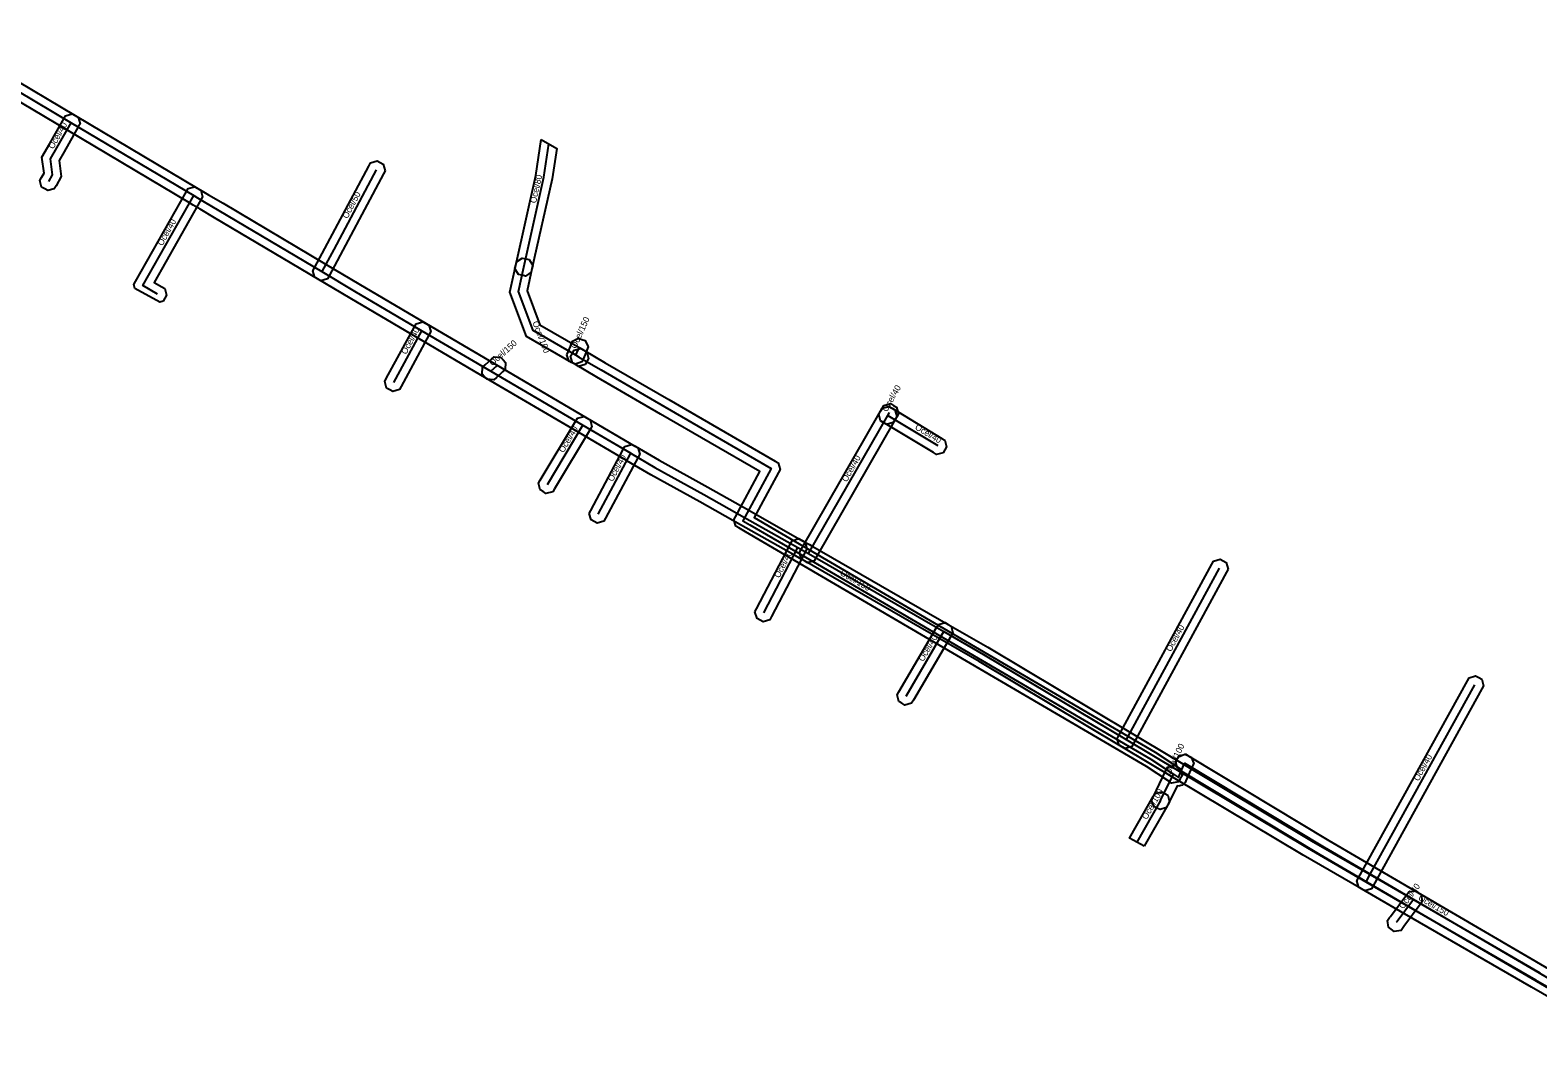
# Model space of a CAD drawing. Extents: x -749340 to -748632, y -965391 to -964902.
# Drawn here: x -749163.1 to -748982.7, y -965119.7 to -964997.5 of the extents above; entities that cross this region are included whole.
import ezdxf

# ---------------------------------------------------------------- set-up
doc = ezdxf.new("R2010")
doc.units = 0
for name, color, linetype in [('1', 7, 'Continuous'), ('18', 7, 'Continuous'), ('20', 7, 'Continuous'), ('28', 7, 'Continuous'), ('30', 7, 'Continuous')]:
    doc.layers.add(name, color=color, linetype=linetype)

msp = doc.modelspace()

# ---------------------------------------------------------------- linework, layer by layer
at = {"layer": '1'}
for points in [[(-749174.95, -964997.45), (-749157.74, -965007.68), (-749143.06, -965016.4), (-749142.6, -965016.68), (-749141.79, -965017.15), (-749140.06, -965018.18), (-749127.73, -965025.51), (-749123.82, -965027.83), (-749115.76, -965032.57), (-749107.52, -965037.41), (-749096.48, -965043.89), (-749090.78, -965047.24), (-749090.73, -965047.26), (-749087.87, -965048.94), (-749082.03, -965052.15), (-749077.15, -965054.91), (-749070.78, -965058.52), (-749069.88, -965059.03), (-749069.5, -965059.24), (-749053.3, -965068.57), (-749048.55, -965071.3), (-749031.48, -965081.51), (-749009.8, -965094.47), (-749002.81, -965098.51), (-748997.7, -965101.46), (-748982.49, -965110.26)], [(-748970.03, -965119.74), (-748983.49, -965111.99), (-748998.7, -965103.2), (-749003.81, -965100.24), (-749010.81, -965096.2), (-749032.5, -965083.23), (-749049.56, -965073.03), (-749054.3, -965070.3), (-749070.49, -965060.98), (-749070.87, -965060.76), (-749071.76, -965060.26), (-749078.14, -965056.65), (-749083, -965053.9), (-749088.86, -965050.68), (-749091.73, -965048.99), (-749091.77, -965048.97), (-749097.5, -965045.61), (-749108.53, -965039.13), (-749116.77, -965034.29), (-749124.83, -965029.55), (-749128.75, -965027.22), (-749141.08, -965019.9), (-749142.81, -965018.87), (-749143.62, -965018.4), (-749144.08, -965018.12), (-749158.76, -965009.4), (-749175.98, -964999.17)]]:
    msp.add_lwpolyline(points, dxfattribs=at)
for points in [[(-749161.99, -965015.45), (-749161.78, -965015.09), (-749161.48, -965014.56), (-749161.73, -965012.67), (-749160.8, -965011.03), (-749159.12, -965008.05), (-749158.91, -965007.69), (-749158.11, -965007.47), (-749157.76, -965007.67), (-749157.39, -965007.88), (-749157.17, -965008.67), (-749157.38, -965009.03), (-749159.06, -965012.02), (-749159.66, -965013.07), (-749159.41, -965014.96), (-749160.04, -965016.07), (-749160.25, -965016.43), (-749161.04, -965016.65), (-749161.4, -965016.45), (-749161.77, -965016.24)], [(-749102, -965010.55), (-749100.13, -965011.62), (-749100.67, -965015.23), (-749103.09, -965026.03), (-749103.18, -965026.43), (-749103.88, -965026.88), (-749104.28, -965026.79), (-749104.69, -965026.7), (-749105.13, -965025.99), (-749105.04, -965025.59), (-749102.64, -965014.87)], [(-749120.65, -965014.3), (-749120.84, -965014.66), (-749127.36, -965026.84), (-749127.56, -965027.2), (-749128.35, -965027.44), (-749128.71, -965027.25), (-749129.08, -965027.05), (-749129.32, -965026.26), (-749129.12, -965025.89), (-749122.6, -965013.72), (-749122.41, -965013.35), (-749121.62, -965013.11), (-749121.25, -965013.31), (-749120.89, -965013.51)], [(-749147.23, -965029.89), (-749147.64, -965030.01), (-749150.61, -965028.36), (-749150.74, -965027.9), (-749150.54, -965027.54), (-749144.44, -965016.77), (-749144.24, -965016.41), (-749143.44, -965016.19), (-749143.08, -965016.39), (-749142.72, -965016.59), (-749142.5, -965017.39), (-749142.7, -965017.75), (-749148.3, -965027.66), (-749147.4, -965028.17), (-749147.04, -965028.37), (-749146.82, -965029.17), (-749147.02, -965029.53)], [(-749097.54, -965037.7), (-749097.9, -965037.49), (-749098.35, -965037.23), (-749103.76, -965034.11), (-749105.76, -965028.82), (-749105.04, -965025.59), (-749104.95, -965025.19), (-749104.25, -965024.74), (-749103.84, -965024.83), (-749103.44, -965024.92), (-749103, -965025.62), (-749103.09, -965026.03), (-749103.68, -965028.67), (-749102.14, -965032.73), (-749097.35, -965035.49), (-749096.9, -965035.76), (-749096.54, -965035.96), (-749096.32, -965036.76), (-749096.53, -965037.12), (-749096.74, -965037.48)], [(-749120.71, -965039.52), (-749120.52, -965039.16), (-749117.14, -965032.95), (-749116.95, -965032.59), (-749116.15, -965032.35), (-749115.79, -965032.55), (-749115.42, -965032.75), (-749115.19, -965033.54), (-749115.39, -965033.9), (-749118.76, -965040.11), (-749118.96, -965040.48), (-749119.75, -965040.71), (-749120.11, -965040.52), (-749120.48, -965040.32)], [(-749098.93, -965036.33), (-749098.76, -965035.95), (-749098.48, -965035.33), (-749098.39, -965035.08), (-749098.25, -965034.69), (-749097.51, -965034.33), (-749097.12, -965034.47), (-749096.72, -965034.61), (-749096.37, -965035.35), (-749096.51, -965035.74), (-749096.63, -965036.08), (-749096.94, -965036.77), (-749097.11, -965037.15), (-749097.89, -965037.44), (-749098.26, -965037.27), (-749098.64, -965037.1)], [(-749073.6, -965050.38), (-749076.51, -965055.79), (-749028.51, -965083.88), (-749025.79, -965085.67), (-749025.45, -965085.89), (-749025.28, -965086.71), (-749025.51, -965087.05), (-749025.74, -965087.4), (-749026.55, -965087.56), (-749026.89, -965087.34), (-749029.56, -965085.58), (-749077.53, -965057.51), (-749078.35, -965057.03), (-749078.7, -965056.83), (-749078.92, -965056.05), (-749078.73, -965055.7), (-749075.82, -965050.28), (-749087.71, -965043.4), (-749095.32, -965038.99), (-749097.9, -965037.49), (-749098.26, -965037.28), (-749098.47, -965036.48), (-749098.26, -965036.12), (-749098.05, -965035.76), (-749097.25, -965035.55), (-749096.9, -965035.76), (-749094.32, -965037.26), (-749086.71, -965041.67), (-749073.98, -965049.04), (-749073.63, -965049.24), (-749073.41, -965050.02)], [(-749109, -965037.8), (-749108.69, -965037.52), (-749107.94, -965036.85), (-749107.63, -965036.57), (-749106.81, -965036.62), (-749106.53, -965036.93), (-749106.25, -965037.23), (-749106.3, -965038.06), (-749106.6, -965038.34), (-749107.35, -965039.01), (-749107.66, -965039.29), (-749108.49, -965039.24), (-749108.77, -965038.94), (-749109.04, -965038.63)], [(-749071.07, -965059.97), (-749070.86, -965059.61), (-749061.38, -965043.07), (-749061.18, -965042.71), (-749060.38, -965042.49), (-749060.02, -965042.7), (-749059.66, -965042.91), (-749059.44, -965043.71), (-749059.65, -965044.07), (-749069.13, -965060.61), (-749069.33, -965060.97), (-749070.13, -965061.19), (-749070.49, -965060.98), (-749070.85, -965060.77)], [(-749061.59, -965043.43), (-749061.38, -965043.07), (-749061.18, -965042.72), (-749060.97, -965042.36), (-749060.17, -965042.15), (-749059.82, -965042.36), (-749059.46, -965042.57), (-749059.24, -965043.36), (-749059.45, -965043.72), (-749059.65, -965044.07), (-749059.86, -965044.43), (-749060.66, -965044.64), (-749061.02, -965044.44), (-749061.38, -965044.23)], [(-749060.35, -965042.5), (-749060, -965042.71), (-749054.03, -965046.31), (-749053.67, -965046.52), (-749053.47, -965047.33), (-749053.69, -965047.68), (-749053.9, -965048.04), (-749054.7, -965048.24), (-749055.06, -965048.02), (-749061.03, -965044.43), (-749061.39, -965044.21), (-749061.59, -965043.41), (-749061.37, -965043.05), (-749061.16, -965042.7)], [(-749102.33, -965051.66), (-749102.11, -965051.31), (-749097.85, -965044.23), (-749097.63, -965043.88), (-749096.83, -965043.68), (-749096.47, -965043.89), (-749096.12, -965044.1), (-749095.92, -965044.91), (-749096.13, -965045.26), (-749100.4, -965052.34), (-749100.61, -965052.7), (-749101.42, -965052.9), (-749101.77, -965052.68), (-749102.12, -965052.47)], [(-749096.25, -965055.29), (-749096.06, -965054.93), (-749092.16, -965047.63), (-749091.96, -965047.27), (-749091.17, -965047.03), (-749090.8, -965047.22), (-749090.44, -965047.42), (-749090.2, -965048.21), (-749090.39, -965048.58), (-749094.29, -965055.87), (-749094.49, -965056.23), (-749095.28, -965056.47), (-749095.65, -965056.28), (-749096.01, -965056.08)], [(-749076.41, -965067.09), (-749076.22, -965066.73), (-749072.16, -965058.93), (-749071.96, -965058.56), (-749071.17, -965058.31), (-749070.81, -965058.5), (-749070.44, -965058.69), (-749070.19, -965059.48), (-749070.38, -965059.85), (-749074.44, -965067.65), (-749074.63, -965068.02), (-749075.42, -965068.27), (-749075.79, -965068.08), (-749076.16, -965067.88)], [(-749019.78, -965061.97), (-749019.97, -965062.33), (-749031.11, -965082.85), (-749031.31, -965083.21), (-749032.1, -965083.45), (-749032.47, -965083.25), (-749032.83, -965083.05), (-749033.07, -965082.26), (-749032.87, -965081.89), (-749021.73, -965061.38), (-749021.54, -965061.02), (-749020.74, -965060.78), (-749020.38, -965060.98), (-749020.01, -965061.18)], [(-749059.39, -965077.01), (-749059.18, -965076.65), (-749054.67, -965068.93), (-749054.46, -965068.57), (-749053.66, -965068.36), (-749053.3, -965068.57), (-749052.94, -965068.78), (-749052.73, -965069.58), (-749052.94, -965069.94), (-749057.45, -965077.66), (-749057.66, -965078.02), (-749058.46, -965078.23), (-749058.82, -965078.02), (-749059.18, -965077.81)], [(-748989.21, -965075.94), (-748989.41, -965076.3), (-749002.44, -965099.86), (-749002.64, -965100.22), (-749003.43, -965100.45), (-749003.8, -965100.25), (-749004.16, -965100.05), (-749004.39, -965099.25), (-749004.19, -965098.89), (-748991.16, -965075.34), (-748990.96, -965074.97), (-748990.17, -965074.74), (-748989.8, -965074.95), (-748989.44, -965075.15)], [(-749025.68, -965087.92), (-749025.9, -965087.89), (-749026.97, -965090.1), (-749027.15, -965090.48), (-749027.93, -965090.75), (-749028.3, -965090.57), (-749028.68, -965090.39), (-749028.95, -965089.61), (-749028.77, -965089.24), (-749027.24, -965086.07), (-749027.05, -965085.66), (-749026.61, -965085.54), (-749026.18, -965085.42), (-749025.91, -965084.79), (-749025.74, -965084.41), (-749024.96, -965084.11), (-749024.59, -965084.28), (-749024.21, -965084.45), (-749023.91, -965085.22), (-749024.08, -965085.6), (-749024.83, -965087.3), (-749024.92, -965087.51), (-749025.25, -965087.8), (-749025.46, -965087.86)], [(-748969.52, -965119.09), (-748969.88, -965118.88), (-748998.11, -965102.38), (-749008.77, -965096.15), (-749025.51, -965086.05), (-749025.86, -965085.84), (-749026.06, -965085.03), (-749025.85, -965084.68), (-749025.63, -965084.32), (-749024.83, -965084.12), (-749024.47, -965084.34), (-749007.75, -965094.43), (-748997.1, -965100.66), (-748968.87, -965117.16), (-748968.51, -965117.37), (-748968.3, -965118.17), (-748968.51, -965118.53), (-748968.72, -965118.88)], [(-749029.85, -965095.12), (-749031.6, -965094.15), (-749028.74, -965089.17), (-749028.53, -965088.81), (-749027.73, -965088.6), (-749027.37, -965088.8), (-749027.01, -965089.01), (-749026.8, -965089.81), (-749027, -965090.17)], [(-748996.56, -965101.78), (-748996.81, -965102.12), (-748998.76, -965104.74), (-748998.86, -965104.87), (-748999.1, -965105.2), (-748999.92, -965105.32), (-749000.26, -965105.07), (-749000.59, -965104.83), (-749000.71, -965104.01), (-749000.46, -965103.67), (-749000.36, -965103.54), (-748998.41, -965100.92), (-748998.16, -965100.59), (-748997.34, -965100.47), (-748997.01, -965100.72), (-748996.68, -965100.96)]]:
    msp.add_lwpolyline(points, close=True, dxfattribs=at)
at = {"layer": '18'}
for points in [[(-749175.47, -964998.31), (-749158.25, -965008.54), (-749143.57, -965017.26), (-749143.11, -965017.54), (-749142.3, -965018.01), (-749140.57, -965019.04), (-749128.24, -965026.36), (-749124.33, -965028.69), (-749116.26, -965033.43), (-749108.02, -965038.27), (-749096.99, -965044.75), (-749091.28, -965048.1), (-749091.23, -965048.13), (-749088.37, -965049.81), (-749082.51, -965053.02), (-749077.65, -965055.78), (-749071.27, -965059.39), (-749070.37, -965059.9), (-749070, -965060.11), (-749053.8, -965069.43), (-749049.06, -965072.17), (-749031.99, -965082.37), (-749010.3, -965095.33), (-749003.31, -965099.38), (-748998.2, -965102.33), (-748982.99, -965111.13), (-748969.53, -965118.87)], [(-749160.91, -965015.58), (-749160.45, -965014.76), (-749160.7, -965012.87), (-749159.93, -965011.52), (-749158.25, -965008.54)], [(-749121.72, -965014.19), (-749126.81, -965023.69), (-749128.24, -965026.36)], [(-749147.89, -965029.04), (-749149.67, -965028.03), (-749143.57, -965017.26)], [(-749119.64, -965039.64), (-749116.26, -965033.43)], [(-749108.02, -965038.27), (-749107.27, -965037.59)], [(-749070, -965060.11), (-749060.52, -965043.57)], [(-749060.52, -965043.57), (-749060.32, -965043.22)], [(-749060.52, -965043.57), (-749054.54, -965047.17)], [(-749101.25, -965051.83), (-749096.99, -965044.75)], [(-749095.18, -965055.4), (-749091.28, -965048.1)], [(-749075.33, -965067.19), (-749071.27, -965059.39)], [(-749020.85, -965061.86), (-749031.99, -965082.37)], [(-749058.32, -965077.15), (-749054.16, -965070.04), (-749053.8, -965069.43)], [(-748990.29, -965075.82), (-749002.82, -965098.49), (-749003.31, -965099.38)]]:
    msp.add_lwpolyline(points, dxfattribs=at)
at = {"layer": '28'}
for points in [[(-749104.06, -965025.81), (-749101.66, -965015.05), (-749101.07, -965011.08)], [(-749097.4, -965036.62), (-749097.85, -965036.36), (-749102.95, -965033.42), (-749104.72, -965028.75), (-749104.06, -965025.81)], [(-749097.85, -965036.36), (-749097.56, -965035.71), (-749097.45, -965035.41)], [(-749097.4, -965036.62), (-749094.82, -965038.12), (-749087.21, -965042.54), (-749074.48, -965049.9), (-749077.85, -965056.17), (-749077.03, -965056.65), (-749071.53, -965059.87), (-749029.03, -965084.72), (-749026.34, -965086.5)], [(-749027.87, -965089.67), (-749026.34, -965086.5), (-749025.74, -965086.9), (-749024.99, -965085.2)], [(-748969.37, -965118.02), (-748997.61, -965101.52), (-749008.26, -965095.29), (-749024.99, -965085.2)], [(-749027.87, -965089.67), (-749030.72, -965094.63)], [(-748997.61, -965101.52), (-748999.56, -965104.14), (-748999.66, -965104.27)]]:
    msp.add_lwpolyline(points, dxfattribs=at)

# ---------------------------------------------------------------- texts
at = {"layer": '20'}
for s, rotation, p in [('Ocel/40', 60.4569, (-749160.37, -965011.75)), ('Ocel/50', 61.8315, (-749125.18, -965020.08)), ('Ocel/40', 60.4945, (-749147.32, -965023.33)), ('Ocel/40', 61.4873, (-749118.15, -965036.33)), ('Ocel/150', 41.9027, (-749107.81, -965037.7)), ('Ocel/40', 59.9706, (-749060.62, -965043.2)), ('Ocel/40', 58.934, (-749099.32, -965048.09)), ('Ocel/40', 328.946, (-749057.33, -965045.17)), ('Ocel/40', 61.8644, (-749093.43, -965051.55)), ('Ocel/40', 60.185, (-749065.43, -965051.6)), ('Ocel/40', 62.4967, (-749073.5, -965063.09)), ('Ocel/40', 61.5057, (-749026.62, -965071.91)), ('Ocel/40', 59.6965, (-749056.26, -965073.09)), ('Ocel/40', 61.0612, (-748997, -965087.4))]:
    msp.add_text(s, height=0.75, rotation=rotation, dxfattribs=at).set_placement(p)
at = {"layer": '30'}
for s, rotation, p in [('Ocel/80', 77.3872, (-749102.61, -965018.22)), ('Ocel/100', 290.7279, (-749103.05, -965032.43)), ('Ocel/150', 65.6554, (-749097.82, -965035.64)), ('Ocel/150', 329.6732, (-749066.31, -965062.6)), ('Ocel/100', 64.2727, (-749026.72, -965086.68)), ('Ocel/100', 60.1011, (-749029.52, -965092)), ('Ocel/40', 53.3298, (-748998.83, -965102.7)), ('Ocel/150', 329.6958, (-748997.1, -965101.5))]:
    msp.add_text(s, height=0.75, rotation=rotation, dxfattribs=at).set_placement(p)

doc.saveas('drawing.dxf')
